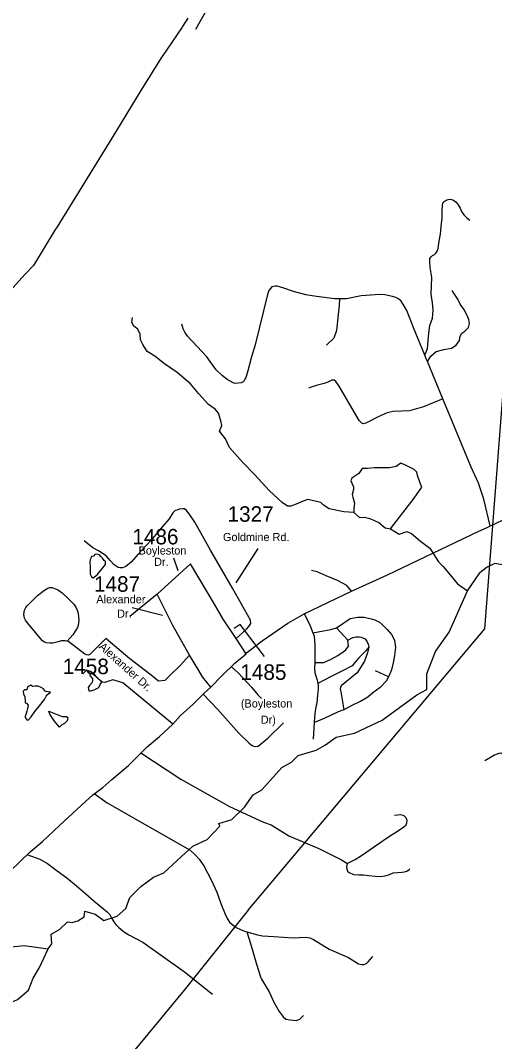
# Model space of a CAD drawing. Extents: x 884530 to 1028605, y 526725 to 653634.
# Drawn here: x 917380 to 921203, y 596749 to 604979 of the extents above; entities that cross this region are included whole.
import ezdxf

# ---------------------------------------------------------------- set-up
doc = ezdxf.new("R2010")
doc.units = 0
for name, color, linetype in [('Exist Boundary Political City Limit New', 7, 'Continuous'), ('Exist Hydrographic Creek Single Shore', 7, 'Continuous'), ('Exist Hydrographic Pond Over 1500 Sq Ft', 7, 'Continuous'), ('Exist Hydrographic Pond Under 1500 Sq Ft', 7, 'Continuous'), ('Exist Road Non-System Type 51', 7, 'Continuous'), ('Exist Road Primary NC Attributed', 7, 'Continuous'), ('Exist Road Secondary Type 51 Attributed', 7, 'Continuous'), ('Exist Road Secondary Type 51 Label', 7, 'Continuous'), ('Exist Road Secondary Type 51 Number Label', 7, 'Continuous'), ('Exist Utilities Electrical Transmission Line', 7, 'Continuous'), ('Map Preparation Boundary City Limit Buffer Line', 7, 'Continuous')]:
    doc.layers.add(name, color=color, linetype=linetype)

msp = doc.modelspace()

# ---------------------------------------------------------------- linework, layer by layer
at = {"layer": 'Exist Boundary Political City Limit New'}
msp.add_lwpolyline([(918729.8, 604996.2), (918686.9, 604930.7), (918682.7, 604924.6), (918522.2, 604689.6), (918515.6, 604678.8), (918352, 604413.5), (918115.6, 604030.3), (917674.9, 603315.8), (917656.8, 603287.8), (917484.4, 603005.1), (917418.4, 602933.2), (917293.8, 602797.2)], dxfattribs=at)
at = {"layer": 'Exist Hydrographic Creek Single Shore'}
for points in [[(920068.3, 601012.6), (919986.7, 601018.2), (919868.6, 601043.5), (919823.6, 601071.6), (919801.1, 601094.1), (919697.1, 601116.7), (919660.5, 601105.4), (919604.3, 601080.1), (919559.3, 601063.2), (919534, 601063.2), (919489, 601094.1), (919387.7, 601187), (919266.8, 601319.2), (919174, 601414.9), (919064.4, 601535.9), (919033.4, 601606.2), (918985.6, 601668.1), (919002.5, 601713.2), (918996.9, 601752.6), (918977.2, 601814.5), (918949.1, 601845.4), (918895.6, 601884.8), (918818.3, 601970.6), (918750.8, 602049.4), (918644, 602142.3), (918542.7, 602212.6), (918464, 602274.5), (918402.1, 602311.1), (918365.6, 602367.4), (918348.7, 602403.9), (918345.9, 602451.8), (918326.2, 602491.2), (918295.3, 602513.7), (918278.4, 602544.6), (918284, 602584)], [(920363.5, 600880.3), (920432.4, 600839.5), (920494.3, 600859.2), (920533.7, 600845.1), (920604, 600783.2), (920679.9, 600727), (920750.2, 600614.4), (920789.6, 600575), (920904.9, 600437.1), (920983.6, 600380.9)], [(921635.3, 600237.5), (921521.5, 600366), (921436.5, 600471.1), (921280.9, 600587.6), (921205.7, 600603.2), (921143.9, 600572.2), (921082.8, 600526.8)], [(920983.6, 600380.9), (921082.8, 600526.8)], [(919255.2, 598737.5), (919325.9, 598777.1), (919486.2, 598957.1), (919564.9, 599002.2), (919618.3, 599055.6), (919764.6, 599097.8), (919839.1, 599141.4), (919926.3, 599203.3), (920072.5, 599234.3), (920295.7, 599338.5), (920575.8, 599542.4), (920657.4, 599587.4), (920656, 599712.6), (920726.3, 599892.7), (920835.8, 600047.6), (920983.6, 600380.9)], [(917604.9, 597496.8), (917633, 597536.2), (917627.4, 597615), (917694.9, 597651.6), (917759.6, 597713.5), (917796.1, 597707.8), (917843.9, 597721.9), (917892.6, 597754.1), (917900.2, 597800.7), (917981.7, 597775.4), (918052, 597724.7), (918159.8, 597758.7), (918230.6, 597821.8), (918261.5, 597909), (918351.5, 597999.1), (918452.7, 598075), (918537.1, 598108.8), (918677.7, 598241), (918770.5, 598322.6), (918885.8, 598378.9), (918987, 598485.8), (918979.7, 598506.8), (919084, 598537.9), (919185.3, 598639.2), (919255.2, 598737.5)], [(917146.3, 597497.6), (917410.9, 597522.1), (917604.9, 597496.8)], [(915122.9, 594520.7), (915242, 594640.7), (915478.8, 594731.1), (915687.9, 594966.5), (916458, 595948.6), (916919.2, 596464.4), (916938.9, 596546), (916874.9, 596616.2), (916901.9, 596671.5), (917233.7, 597032.6), (917357.4, 597088.8), (917445.4, 597162.6), (917482.4, 597260.3), (917534.6, 597344.9), (917604.9, 597496.8)]]:
    msp.add_lwpolyline(points, dxfattribs=at)
at = {"layer": 'Exist Hydrographic Pond Over 1500 Sq Ft'}
for points in [[(920363.5, 600880.3), (920554.8, 601127.9), (920616.6, 601218), (920602.6, 601248.9), (920580.1, 601310.8), (920575.8, 601337.5), (920553.3, 601360), (920478.8, 601398), (920447.9, 601412.1), (920408.5, 601384), (920355.1, 601372.7), (920293.2, 601372.7), (920231.4, 601372.7), (920177.9, 601367.1), (920135.8, 601367.1), (920107.6, 601327.7), (920051.4, 601291.1), (920043, 601268.6), (920065.5, 601220.8), (920065.5, 601198.3), (920054.2, 601158.9), (920059.8, 601136.4), (920073.9, 601088.5), (920068.3, 601043.5), (920068.3, 601012.6), (920113.3, 600973.2), (920154.7, 600976.7), (920196.9, 600965.4), (920270.7, 600933.8), (920320.7, 600889.5)], [(917438.3, 599607.8), (917431.3, 599583.9), (917411.6, 599583.9), (917403.1, 599572.6), (917405.9, 599550.1), (917414.4, 599530.4), (917418.6, 599495.3), (917418.6, 599479.8), (917429.8, 599475.6), (917441.1, 599460.1), (917438.3, 599433.4), (917431.3, 599410.8), (917422.8, 599382.7), (917418.6, 599371.5), (917418.6, 599360.2), (917434.1, 599340.5), (917445.3, 599343.3), (917467.8, 599367.2), (917495.9, 599409.4), (917533.9, 599455.9), (917573.3, 599506.5), (917588.7, 599533.2), (917595.8, 599544.5), (917611.2, 599555.8), (917622.5, 599564.2), (917604.2, 599568.4), (917581.7, 599571.2), (917566.2, 599590.9), (917546.5, 599602.2), (917524.1, 599614.8), (917500.1, 599614.8), (917476.2, 599612), (917465, 599621.9)]]:
    msp.add_lwpolyline(points, close=True, dxfattribs=at)
at = {"layer": 'Exist Hydrographic Pond Under 1500 Sq Ft'}
for points in [[(917965.5, 600487.1), (917999.3, 600509.6), (918065.4, 600595.4), (918065.4, 600615.1), (918065.4, 600622.1), (918055.5, 600626.4), (918042.9, 600646.1), (918027.4, 600657.3), (918016.2, 600672.8), (917996.5, 600677), (917981, 600674.2), (917969.8, 600661.5), (917954.3, 600658.7), (917950.1, 600650.3), (917943, 600634.8), (917938.8, 600619.3), (917941.6, 600568.7), (917941.6, 600537.7), (917941.6, 600515.2), (917952.9, 600495.5)], [(917944.5, 599575.4), (917975.4, 599583.9), (918013.4, 599602.2), (918021.8, 599626.1), (918037.3, 599645.8), (917988, 599692.2), (917955.7, 599714.7), (917937.4, 599704.9), (917959.9, 599673.9), (917959.9, 599658.5), (917957.1, 599643), (917937.4, 599619.1), (917926.2, 599603.6), (917929, 599588.1), (917931.8, 599576.9)], [(917608.4, 599410.8), (917715.3, 599370), (917735, 599370), (917750.4, 599370), (917761.7, 599360.2), (917756, 599333.5), (917736.4, 599313.8), (917712.5, 599302.5), (917694.2, 599282.8), (917653.4, 599332.1), (917616.8, 599386.9)]]:
    msp.add_lwpolyline(points, close=True, dxfattribs=at)
at = {"layer": 'Exist Road Non-System Type 51'}
for p, q in [((920785.3, 601930.5), (920660.6, 602230.6)), ((918482.1, 600355.6), (918262.9, 600175.6)), ((920020.3, 599983.1), (919927.1, 600084.3)), ((920346.7, 599688.9), (920242.8, 599737.3)), ((919747.4, 599319.4), (919738.8, 599185.6))]:
    msp.add_line(p, q, dxfattribs=at)
for points in [[(919231, 605860.6), (919120.3, 605706.5), (919083.4, 605640.6), (919045.3, 605544.5), (919001.8, 605369.3), (918941.2, 605195.4), (918896.4, 605092.7), (918791, 604907)], [(920640.1, 602280), (920660.8, 602335.8), (920667.1, 602399), (920671.3, 602458.4), (920680.6, 602521), (920701.6, 602580), (920708.2, 602645.2), (920701.1, 602703.5), (920691.7, 602771.9), (920693.3, 602840.3), (920697.3, 602906.7), (920682.5, 602987.9), (920680.3, 603036.5), (920681.9, 603061.5), (920691.5, 603073.3), (920701.6, 603083.9), (920718.1, 603093.1), (920729.8, 603102.3), (920738.9, 603120.5), (920746.7, 603140.3), (920751.3, 603161.5), (920755.7, 603199.7), (920765.4, 603257.2), (920771.7, 603319.1), (920780.3, 603388.8), (920779.7, 603442.4), (920781.5, 603486.6), (920786.3, 603508.8), (920795.9, 603520.6), (920811.1, 603531), (920827.3, 603536.6), (920848.3, 603538.2), (920872.3, 603529.4), (920892.3, 603513.2), (920909.3, 603493.2), (920924.3, 603467), (920935.9, 603438.2), (920954.3, 603411.2), (920978.7, 603388.6), (921001.7, 603370.3)], [(919951.6, 602734.9), (919915.8, 602734.9), (919767, 602753.8), (919681.1, 602768), (919581.1, 602793.1), (919494.4, 602824), (919449.4, 602836.1), (919431.1, 602837.5), (919407.3, 602831.1), (919382.8, 602802.4), (919371.3, 602771.1), (919271.6, 602364.1), (919242.4, 602267.8), (919214.5, 602154.3), (919200.2, 602108.2), (919184.6, 602073.1), (919176.2, 602065.4), (919160.1, 602059.4), (919111.2, 602052.8), (919094.7, 602058.8), (919047.7, 602085.5), (919008.8, 602115.2), (918958.2, 602164.2), (918883.8, 602269), (918726.4, 602434.8), (918705.9, 602465.6), (918691.6, 602494.2), (918681.3, 602531.2)], [(920660.6, 602230.6), (920689, 602272.8), (920731.3, 602310.5), (920792.7, 602327), (920855.5, 602338.4), (920893.3, 602362.8), (920920.1, 602399.4), (920925.9, 602435.2), (920937.5, 602457.8), (920962.8, 602475.8), (920992.5, 602504.6), (921000, 602535.4), (920995.7, 602569), (920978.1, 602605.6), (920954.8, 602651.2), (920924.9, 602692.9), (920907.2, 602731.6), (920880, 602773.1), (920861.7, 602803.6)], [(919951.6, 602734.9), (919950.5, 602685.1), (919928.2, 602481), (919906.1, 602418.8), (919848.4, 602361.1)], [(920640.1, 602280), (920550.7, 602495.5), (920494.3, 602640.7), (920469.5, 602688), (920448.7, 602717.6), (920429.2, 602734.7), (920406.5, 602746.2), (920378.9, 602755.3), (920316.9, 602767), (920277.5, 602769.3), (920127.3, 602759.3), (920009.4, 602734.8), (919951.6, 602734.9)], [(920660.6, 602230.6), (920650.3, 602252.3), (920640.1, 602280)], [(920785.3, 601930.5), (920629.3, 601864.3), (920517.2, 601833.4), (920453.3, 601831.1), (920384.6, 601827.7), (920336.4, 601816.8), (920262.8, 601784.9), (920165.6, 601733.2), (920143.2, 601728.1), (920131.3, 601732), (920110.4, 601755.6), (919950.8, 602031.7), (919923.3, 602068.4), (919910.2, 602080.1), (919889.3, 602078.8), (919857.9, 602064.4), (919829.1, 602053.9), (919775.5, 602038.2), (919715.2, 602019.9), (919703.1, 602014.1)], [(921166.5, 600904.9), (921116.1, 601119.7), (921072.2, 601248.9), (921013.1, 601378.3), (920857.7, 601756), (920785.3, 601930.5)], [(918784.8, 600935.2), (918741, 601001.3), (918719.9, 601028), (918701.6, 601043.5), (918690.4, 601043.5), (918663.6, 601040.7), (918639.7, 601032.2), (918628.5, 601029.4), (918608.8, 601009.7), (918577.9, 600963.3), (918527.3, 600904.2), (918485.1, 600850.8), (918431.6, 600787.5), (918326.2, 600673.5), (918272.8, 600611.6), (918246, 600590.5), (918230.6, 600579.2), (918202.5, 600568), (918184.2, 600568), (918168.7, 600570.8), (918136.4, 600590.5), (918102.6, 600625.7), (918070.3, 600663.7), (918008.4, 600703), (917964.1, 600727.7), (917895.2, 600785.3)], [(920047.9, 600380.2), (920012.7, 600425.2), (919935.4, 600464.6), (919844.8, 600501.5), (919772.1, 600535.4), (919725.3, 600545.9)], [(918068.9, 599998.2), (917938.3, 599868.4), (917926.9, 599864), (917913.1, 599865.3), (917900.5, 599871), (917770.3, 599970.8), (917755.6, 599976.9), (917755.2, 599977.1), (917739.4, 599979), (917723, 599980.2), (917710.4, 599978.3), (917685.1, 599969.5), (917640.3, 599958.8), (917616.3, 599959.6), (917588.5, 599963.2), (917571.8, 599969.7), (917557.9, 599979), (917435, 600125.4), (917420.5, 600145.7), (917413.6, 600160.8), (917409.8, 600177.9), (917408.5, 600191.1), (917409.8, 600208.8), (917413.6, 600226.5), (917423.9, 600246.5), (917435.6, 600260.5), (917517.1, 600342.9), (917575, 600387.9), (917601.7, 600403.9), (917615.7, 600408.4), (917632.1, 600407.7), (917649.1, 600403.9), (917662.4, 600398.9), (917678.7, 600391.9), (917715.4, 600365.4), (917764, 600321.2), (917811.1, 600274.4), (917826.6, 600250.5), (917838.6, 600225.2), (917845.5, 600201.9), (917848.6, 600170.9), (917849.9, 600145.7), (917848.6, 600121), (917845.5, 600103.4), (917839.2, 600085.7), (917827.8, 600064.2), (917801.9, 600026.9), (917755.6, 599976.9), (917754.6, 599975.8)], [(919668.3, 600197.3), (919711, 600113.3), (919737.3, 600042.9)], [(919927.1, 600084.3), (919986.9, 600123.6), (920038.7, 600159.4), (920100.3, 600169.4), (920150.7, 600169.6), (920206.4, 600157), (920237.4, 600148.2), (920259.2, 600137.9), (920275.4, 600128), (920298.9, 600107), (920337.8, 600069.2), (920372.1, 600029.6), (920395.7, 599984.9), (920403, 599925.1), (920396.5, 599861.6), (920385, 599800.7), (920372.8, 599745.5), (920353.4, 599700.5), (920346.7, 599688.9)], [(919737.3, 600042.9), (919822, 600060.5), (919882.7, 600070.1), (919927.1, 600084.3)], [(919737.3, 600042.9), (919747.2, 600015.9), (919752.7, 599947.4), (919754.6, 599889.6), (919753.9, 599819), (919753.3, 599803.6)], [(920020.3, 599983.1), (920058.8, 600005.6), (920087.2, 600010.1), (920110.6, 600010.1), (920125.9, 600007.3), (920157.9, 599993.8), (920175.5, 599971.5), (920182.7, 599950.7), (920189.8, 599928.3)], [(919753.3, 599803.6), (919824.8, 599805), (919885.9, 599830), (919937.7, 599860.4), (919981.6, 599889.2), (920003.5, 599905.2), (920024.8, 599935.5), (920020.3, 599983.1)], [(920189.8, 599928.3), (920160.7, 599894.9), (920126.7, 599859.4), (920108.3, 599841.7), (920089.7, 599819.3), (920053.5, 599777.7), (919982.6, 599740.4), (919897.2, 599695.5), (919828.6, 599660.9), (919776.6, 599635.8)], [(920189.8, 599928.3), (920177.6, 599883.3), (920153, 599813.9), (920096, 599722.2), (919967, 599615.1), (919960.2, 599602.4), (919958.6, 599588.1), (919964.1, 599566.5), (919988.4, 599423.8)], [(918604.9, 599310.7), (918204.9, 599639.1), (918124.5, 599664.8), (918076.3, 599648.7), (918060.2, 599642.3), (918039.4, 599645.8), (918018.5, 599664.8), (917995.9, 599687.3), (917973.5, 599709.7), (917944.6, 599732.2), (917912.4, 599741.9), (917883.5, 599713)], [(919080.1, 599772.9), (919134.8, 599720.1), (919172.1, 599681.6), (919211.2, 599640), (919243.8, 599604.7), (919294.6, 599544.8), (919323.3, 599513.4)], [(919753.3, 599803.6), (919751.6, 599759.2), (919752.6, 599721.7), (919772.2, 599662), (919776.6, 599635.8)], [(920346.7, 599688.9), (920327.3, 599655.1), (920279.9, 599601.9), (920221.1, 599558.9), (920179.8, 599523.7), (920121.9, 599491), (920113.5, 599486.6), (920056.7, 599459.9), (919988.4, 599423.8)], [(919776.6, 599635.8), (919779, 599621.8), (919780.4, 599585.6), (919774.3, 599543.1), (919769.5, 599475.9), (919763, 599458.5), (919755.9, 599416), (919750.3, 599363.1), (919747.4, 599319.4)], [(918850.8, 599551.1), (918969.4, 599427.3), (919141.7, 599235.6), (919222.1, 599157.9), (919238.9, 599141.2), (919252.8, 599132.9), (919272.2, 599127.3), (919297.9, 599130.3), (919373.3, 599193.3), (919500.6, 599318.4)], [(919988.4, 599423.8), (919942.9, 599405.4), (919869.4, 599371.4), (919810.6, 599344.2), (919747.4, 599319.4)], [(921836.7, 599141.1), (921822.7, 599115.5), (921794.6, 599074.6), (921661.7, 598948.1), (921535.2, 598817.8), (921475.2, 598771.7), (921457.3, 598757.7), (921440.7, 598753.9), (921426.6, 598753.9), (921412.6, 598767.9), (921398.5, 598782), (921362.8, 598868.9), (921282.3, 599035), (921272.1, 599059.3), (921264.4, 599069.5), (921254.2, 599073.3), (921236.3, 599070.8), (921201.8, 599056.7), (921123.9, 599010.7)], [(918351.4, 599077), (918674, 598864.6), (919066.1, 598642.8), (919339.3, 598517.5), (919400.3, 598495), (919545, 598408.3), (919786, 598305.4), (919967.4, 598214.8), (919995.6, 598196.7), (920014.7, 598183.9)], [(917973.8, 598747.7), (918079.2, 598674.2), (918748, 598292.5), (918791.4, 598251.6), (918821.7, 598218.4), (918859.8, 598166.1), (918919, 598053.3), (918962.5, 597952.9), (918996.2, 597862.4), (919030.8, 597775.1), (919046.1, 597741.2), (919065.9, 597711.5), (919095.5, 597687.5), (919118.6, 597668.7), (919154.8, 597652.3), (919185.4, 597639.5), (919206.2, 597633.4)], [(920014.7, 598183.9), (920077.4, 598215.8), (920130.1, 598249.4), (920225.4, 598315.4), (920278.8, 598351.5), (920323.5, 598381.8), (920376.9, 598417.9), (920421, 598446), (920471.4, 598479.3), (920490.9, 598495.1), (920495.7, 598511.6), (920498.2, 598532), (920490.9, 598553.5), (920475.1, 598566.6), (920465, 598572.3), (920444.8, 598576.7), (920396.4, 598570.2)], [(917432.7, 598257.1), (917536.4, 598218.5), (917598.4, 598183.6), (917675.2, 598124.3), (917753.1, 598068.3), (917833.3, 598003.5), (917906.7, 597940.7), (917974.9, 597879.5), (918048.7, 597819.6), (918080, 597795), (918101.1, 597771.9), (918116.5, 597741.2), (918131.8, 597713.8), (918149.4, 597691.8), (918171.4, 597672.1), (918212, 597637), (918253.7, 597610.6), (918367.8, 597549.1), (918703.7, 597309.8), (918929.8, 597132.1)], [(920014.7, 598183.9), (920009.5, 598157.3), (920011, 598137.8), (920016, 598123.4), (920031.5, 598111.2), (920065.1, 598096.9), (920108.3, 598093.5), (920145.9, 598093.3), (920190.1, 598086.5), (920241, 598080.9), (920280.1, 598079.9), (920319.3, 598083.9), (920354.8, 598095.5), (920384, 598107.7), (920454.1, 598114), (920476.5, 598118.3), (920500.3, 598126.3), (920519.8, 598140)], [(919206.2, 597633.4), (919290.7, 597608.7), (919331.1, 597601.6), (919423.7, 597595.2), (919578.3, 597584.4), (919681.6, 597591.8), (919713.5, 597585.4), (919743.1, 597572.7), (919868.2, 597493.1), (920024.3, 597425.3), (920104.5, 597376), (920131.5, 597369.7), (920147.4, 597370.7), (920168.7, 597379.3), (920182.4, 597392), (920220.6, 597433.4)], [(919206.2, 597633.4), (919234.3, 597540.5), (919283.9, 597374.1), (919316, 597272), (919324.8, 597251.6), (919386.1, 597149.4), (919424, 597067.6), (919464.9, 596991.8), (919497, 596948), (919520.3, 596930.5), (919555.4, 596924.6), (919602.1, 596918.8), (919631.2, 596930.5), (919663.4, 596959.7)]]:
    msp.add_lwpolyline(points, dxfattribs=at)
at = {"layer": 'Exist Road Primary NC Attributed'}
for points in [[(919193, 599875.1), (919328, 599977.8), (919536.1, 600121.3), (919668.3, 600197.3), (920047.9, 600380.2), (920338.2, 600511.7), (921076.5, 600862.2), (921143.4, 600891), (921351, 600992.6)], [(918913.9, 599604.8), (919007.7, 599700.7), (919109.5, 599798.4), (919198.6, 599875.1)], [(917296.9, 598123.2), (917459.6, 598277.7), (917557.4, 598362.2), (917695.5, 598490.7), (917873.5, 598653.6), (917964.9, 598736.5), (918043.3, 598798), (918118.1, 598860.8), (918251.4, 598973.3), (918400.5, 599123.9), (918501.8, 599207.1), (918609.2, 599306.9), (918670.6, 599376), (918773.7, 599469.7), (918861.9, 599558), (918913.9, 599604.8)]]:
    msp.add_lwpolyline(points, dxfattribs=at)
at = {"layer": 'Exist Road Secondary Type 51 Attributed'}
for points in [[(919118.5, 599997.5), (919202.9, 600072.1), (919222.5, 600094.6), (919238, 600118.5), (919236, 600146.4), (919089.3, 600402.1), (918912.6, 600709.4), (918784.8, 600935.2)], [(918751.3, 600599), (918482.1, 600355.6)], [(919118.5, 599997.5), (919015.1, 600154.4), (918943.4, 600274), (918751.3, 600599)], [(918743.1, 599862.4), (918608.1, 600103), (918482.1, 600355.6)], [(918743.1, 599862.4), (918666.6, 599780.4), (918576.7, 599690.4), (918543, 599660.4), (918494.2, 599652.9), (918434.3, 599701.6), (918261.9, 599832.9), (918068.9, 599998.2)], [(919198.6, 599875.1), (919118.5, 599997.5)], [(918913.9, 599604.8), (918848.5, 599688), (918817.6, 599740.1), (918743.1, 599862.4)]]:
    msp.add_lwpolyline(points, dxfattribs=at)
at = {"layer": 'Exist Road Secondary Type 51 Label'}
for points in [[(918614.3, 600648.9), (918648.3, 600546.9)], [(919293.7, 600724.1), (919117.4, 600445.5)], [(918281.3, 600247.7), (918526, 600186.5)], [(919348.2, 599853.3), (919151.1, 600111.7), (919103.5, 600077.7)]]:
    msp.add_lwpolyline(points, dxfattribs=at)
at = {"layer": 'Exist Utilities Electrical Transmission Line'}
for points in [[(919215.5, 597808.3), (921124.3, 600075), (921355.3, 603059.1), (925357.2, 607735.8), (926768.3, 610919.4), (927159.2, 611823.9), (928300.4, 613120.2), (929404.2, 614372.6), (929377.4, 616031), (929346.3, 617714.4), (929345.2, 618021.6), (929852.2, 621210.3), (929810.4, 621334.5), (929197.7, 622629.2), (928034.6, 624800), (927482.4, 626024.4), (927504.2, 627587.8), (927629.3, 629272), (927654.5, 630965.2), (927677.4, 631260.1), (927996.2, 631739.4), (928303.4, 632200.5), (928506, 632490), (928981.9, 633140.2)], [(919215.9, 597808.3), (918700.8, 597162.4), (918354.8, 596746.6), (917784.8, 596061.1), (916993, 595114.9), (916195, 594155.6), (915366.6, 593139.2), (914531.4, 592129.6)]]:
    msp.add_lwpolyline(points, dxfattribs=at)
at = {"layer": 'Map Preparation Boundary City Limit Buffer Line'}
msp.add_lwpolyline([(918729.8, 604996.2), (918686.9, 604930.7), (918682.7, 604924.6), (918522.2, 604689.6), (918515.6, 604678.8), (918352, 604413.5), (918115.6, 604030.3), (917674.9, 603315.8), (917656.8, 603287.8), (917484.4, 603005.1), (917418.4, 602933.2), (917293.8, 602797.2)], dxfattribs=at)

# ---------------------------------------------------------------- texts
at = {"layer": 'Exist Road Secondary Type 51 Label'}
for s, height, p in [('Goldmine Rd.', 65.617, (919012.8, 600782.7)), ('Boyleston', 65.62, (918332.7, 600674.2)), ('Dr.', 65.62, (918457.8, 600583)), ('Alexander', 65.62, (917992.4, 600281.6)), ('Dr.', 65.62, (918159.3, 600165)), ('(Boyleston', 65.62, (919157.4, 599441.3)), ('Dr)', 65.62, (919317.3, 599310.4))]:
    msp.add_text(s, height=height, dxfattribs=at).set_placement(p)
msp.add_text('Alexander Dr.', height=65.617, rotation=318.13695, dxfattribs=at).set_placement((918007, 599924))
at = {"layer": 'Exist Road Secondary Type 51 Number Label'}
for s, p in [('1327', (919049.6, 600938.5)), ('1486', (918282.4, 600756.1)), ('1487', (917972.9, 600374.5)), ('1458', (917720.9, 599710.4)), ('1485', (919152.7, 599664.2))]:
    msp.add_text(s, height=125, dxfattribs=at).set_placement(p)

doc.saveas('drawing.dxf')
